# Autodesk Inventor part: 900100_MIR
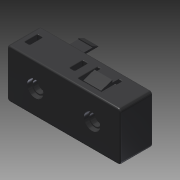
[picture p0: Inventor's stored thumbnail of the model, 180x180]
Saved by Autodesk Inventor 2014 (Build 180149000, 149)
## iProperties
Created: 2007-12
Part Number: 900100_MIR
Material: Acetal Resin, Black
Description: 1200 POWER SEAT SWITCH CONTROL
Document SubType Name: Modeling
Designer: jjohnson
Mass: 54.0389 g
Surface Area: 125.096 cm^2
Volume: 37.922 cm^3
Density: 1.425 g/cm^3
Appearance: Dark Gray
Component Category: Electrical
Author: EP
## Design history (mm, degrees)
node "900100" dims "d0" = 10
  sketch "Sketch1"
    geometry: L1 (35, 15)-(-35, 15) reference; L2 (-35, 15)-(-35, -15) reference; L3 (-35, -15)-(35, -15) reference; L4 (35, -15)-(35, 15) reference; 1 further point
  sketch "Sketch2"
    geometry: C1 r 1.905 at (25, 6.35) reference; 1 further point
  sketch "Sketch3"
    geometry: C1 r 1.905 at (0, 0) reference; C2 r 0.711 at (0, 0) reference; C3 r 0.635 at (0, 0) reference
  sketch "Sketch4"
    geometry: C1 r 1.905 at (0, 0) reference; C2 r 1.27 at (0, 0) reference
  sketch "Sketch5"
    geometry: L1 (4.191, 20)-(8.509, 20) reference; L2 (4.191, 20)-(8.509, 20) reference; L3 (-2.159, 20)-(2.159, 20) reference; L4 (-2.159, 20)-(2.159, 20) reference; L5 (-8.509, 20)-(-4.191, 20) reference; L6 (-8.509, 20)-(-4.191, 20) reference; L7 (-15, 20)-(15, 20) reference; L8 (15, 20)-(-15, 20) reference; L9 (-8.509, 20)-(-4.191, 20) reference; L10 (-8.509, 20)-(-4.191, 20) reference; L11 (-2.159, 20)-(2.159, 20) reference; L12 (-2.159, 20)-(2.159, 20) reference; L13 (4.191, 20)-(8.509, 20) reference; L14 (4.191, 20)-(8.509, 20) reference; L15 (-9.525, 20)-(-9.525, 32.89) reference; L16 (-9.525, 32.89)-(-11.39, 28.89) reference; L17 (-11.39, 28.89)-(-10.795, 28.89) reference; L18 (-10.795, 28.89)-(-10.795, 20) reference; L19 (-10.795, 20)-(-9.525, 20) reference; 1 further point
  sketch "Sketch6"
    geometry: L1 (-9.025, 20)-(-10.795, 20) reference; L2 (-10.795, 20)-(-9.025, 20) reference; L3 (4.191, 20)-(8.509, 20) reference; L4 (4.191, 20)-(8.509, 20) reference; L5 (-2.159, 20)-(2.159, 20) reference; L6 (-2.159, 20)-(2.159, 20) reference; L7 (-8.509, 20)-(-4.191, 20) reference; L8 (-8.509, 20)-(-4.191, 20) reference; L9 (-15, 20)-(15, 20) reference; L10 (15, 20)-(-15, 20) reference; L11 (-8.509, 20)-(-4.191, 20) reference; L12 (-8.509, 20)-(-4.191, 20) reference; L13 (-2.159, 20)-(2.159, 20) reference; L14 (-2.159, 20)-(2.159, 20) reference; L15 (4.191, 20)-(8.509, 20) reference; L16 (4.191, 20)-(8.509, 20) reference; L17 (8.89, 20)-(8.89, 26.35) reference; L18 (8.89, 26.35)-(8.539, 26.35) reference; L19 (8.539, 26.35)-(9.449, 28.85) reference; L20 (9.449, 28.85)-(9.449, 20) reference; L21 (9.449, 20)-(8.89, 20) reference; 1 further point
  sketch "Sketch7"
    geometry: L1 (15.475, 21)-(15.475, -21) reference; L2 (30.842, 6.35)-(30.08, 6.35) reference; L3 (30.08, 6.35)-(30.08, -6.35) reference; L4 (30.08, -6.35)-(30.842, -6.35) reference; L5 (30.842, -6.35)-(30.842, 6.35) reference; 1 further point
  sketch "Sketch8"
    geometry: L1 (-7.158, -6.92)-(-4.158, -6.92) reference; L2 (-4.158, -6.92)-(-4.158, -14.92) reference; L3 (-4.158, -14.92)-(-7.158, -14.92) reference; L4 (-7.158, -14.92)-(-7.158, -6.92) reference; L5 (0, -20)-(-70, -20) reference; L6 (-19.525, 4)-(-19.525, -24) reference; L7 (-4.158, -20)-(-4.158, -10) reference; L8 (-4.158, -20)-(-4.158, -10) reference
  sketch "Sketch9"
    geometry: C1 r 5 at (17.5, 0) reference; C2 r 5 at (-17.5, 0) reference; 1 further point
  sketch "Sketch10"
    geometry: C1 r 5 at (0, 0) reference; C2 r 3.5 at (0, 0) reference; C3 r 4.25 at (0, 0) reference
  sketch "Sketch11"
    geometry: C1 r 2.159 at (25, -6.35) reference
  sketch "Sketch12"
    geometry: C1 r 2.159 at (25, 0) reference
  sketch "Sketch13"
    geometry: C1 r 2.159 at (25, 6.35) reference
  sketch "Sketch14"
    geometry: C1 r 2.159 at (18.65, 0) reference
  sketch "Sketch15"
    geometry: C1 r 2.159 at (18.65, 6.35) reference
  sketch "Sketch16"
    geometry: C1 r 2.159 at (12.3, -6.35) reference
  sketch "Sketch17"
    geometry: C1 r 2.159 at (12.3, 0) reference
  sketch "Sketch18"
    geometry: C1 r 2.159 at (12.3, 6.35) reference
  sketch "Sketch19"
    geometry: C1 r 2.159 at (5.95, -6.35) reference
  sketch "Sketch20"
    geometry: C1 r 2.159 at (5.95, 0) reference
  sketch "Sketch21"
    geometry: C1 r 2.159 at (5.95, 6.35) reference
  sketch "Sketch22"
    geometry: L1 (-33, 25.489)-(-33, -19.933) reference; L2 (-38, 15)-(-53, 15) reference; L3 (-53, 15)-(-53, 3) reference; L4 (-53, 3)-(-38, 3) reference; L5 (-38, 3)-(-38, 15) reference; L6 (-31.63, -1)-(-33.392, -1) reference; L7 (-33.392, -1)-(-31.63, -1) reference; L8 (-24.891, -1)-(-29.209, -1) reference; L9 (-12.191, -1)-(-16.509, -1) reference; L10 (-24.891, -1)-(-29.209, -1) reference; L11 (-12.191, -1)-(-16.509, -1) reference; L12 (-24.891, -1)-(-29.209, -1) reference; L13 (-12.191, -1)-(-16.509, -1) reference; L14 (-5.841, -1)-(-10.159, -1) reference; L15 (-18.541, -1)-(-22.859, -1) reference; L16 (-5.841, -1)-(-10.159, -1) reference; L17 (-18.541, -1)-(-22.859, -1) reference; L18 (-5.841, -1)-(-10.159, -1) reference; L19 (-18.541, -1)-(-22.859, -1) reference; L20 (-13.08, -1)-(-21.97, -1) reference; L21 (-13.08, -1)-(-21.97, -1) reference; L22 (-19.43, -1)-(-15.62, -1) reference; L23 (-19.43, -1)-(-15.62, -1) reference; L24 (-1.658, -1)-(-3.42, -1) reference; L25 (-3.42, -1)-(-1.658, -1) reference; L26 (-66, -1)-(0, -1) reference; L27 (-67, -1)-(-66, -1) reference; L28 (-66, -1)-(-67, -1) reference; L29 (0, -1)-(-66, -1) reference; L30 (1, -1)-(0, -1) reference; L31 (0, -1)-(1, -1) reference
  sketch "Sketch23"
    geometry: L1 (-1.465, -1.5)-(-12, -1.5) reference; L2 (-16, -8.15)-(-16, -21.85) reference; L3 (-16, -21.85)-(-16, -8.15) reference; L4 (-16, -23.509)-(-16, -19.191) reference; L5 (-16, -23.509)-(-16, -19.191) reference; L6 (-16, -17.159)-(-16, -12.841) reference; L7 (-16, -17.159)-(-16, -12.841) reference; L8 (-16, -10.809)-(-16, -6.491) reference; L9 (-16, -10.809)-(-16, -6.491) reference; L10 (-16, -10.809)-(-16, -6.491) reference; L11 (-16, -10.809)-(-16, -6.491) reference; L12 (-16, -17.159)-(-16, -12.841) reference; L13 (-16, -17.159)-(-16, -12.841) reference; L14 (-16, -23.509)-(-16, -19.191) reference; L15 (-16, -23.509)-(-16, -19.191) reference; L16 (-16, -5.975)-(-16, -4.205) reference; L17 (-16, -4.205)-(-16, -5.975) reference; L18 (-16, -23.39)-(-16, -24.449) reference; L19 (-16, -24.449)-(-16, -23.39) reference; L20 (-16, -8.15)-(-16, -21.85) reference; L21 (-16, -21.85)-(-16, -8.15) reference; L22 (-16, -28)-(-16, -29) reference; L23 (-16, -2)-(-16, -28) reference; L24 (-16, -1)-(-16, -2) reference; L25 (-16, -2)-(-16, -1) reference; L26 (-16, -28)-(-16, -2) reference; L27 (-16, -29)-(-16, -28) reference; L28 (0, 0)-(0, -4) reference; L29 (0, 0)-(0, -4) reference; L30 (-12, 0)-(-12, -4) reference; L31 (-12, 0)-(-12, -4) reference; L32 (-12, 0)-(-8, 0) reference; L33 (-8, 0)-(-8, 1.5) reference; L34 (-8, 1.5)-(-1.338, -0.721) reference; A1 r 0.4 centre (-1.465, -1.1) between (-1.465, -1.5) and (-1.338, -0.721) reference; 1 further point
  workplane "Work Plane1"
  workplane "Work Plane2"
  node "1"
  node "2"
  node "3"
  node "4"
  node "5"
  node "6"
  node "7"
  node "8"
  node "9"
  node "10"
  node "11"
  node "12"
  sketch "Sketch24"
    geometry: L1 (-98.674, -18.302)-(-98.674, -36.302) reference; L2 (-92.674, -36.302)-(-92.674, -18.302) reference; C1 r 15 at (-28.39, -30.958) reference; A1 r 3 centre (-95.674, -36.302) between (-98.674, -36.302) and (-92.674, -36.302) reference; A2 r 3 centre (-95.674, -18.302) between (-92.674, -18.302) and (-98.674, -18.302) reference; 4 further points; 1 other entity
    constraints: 1 other
body "Solid1"
tag "TaggingFeature2"
workplane "Work Plane3"
feature "DerivedBody::D-900100.ipt" dims "d0" = 10
